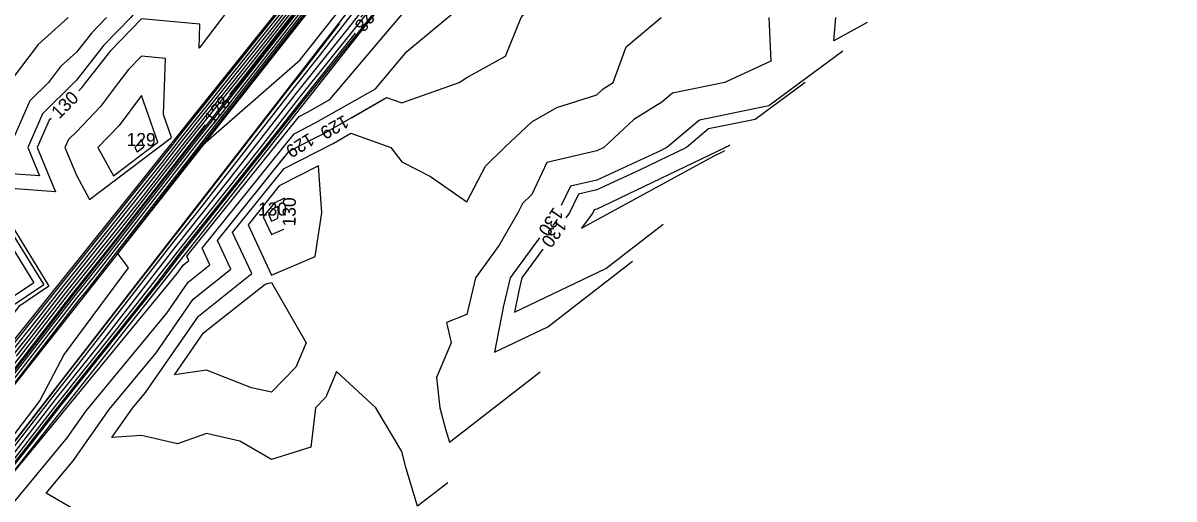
# Model space of a CAD drawing. Extents: x 2354170 to 2357230, y 866100 to 868290.
# Drawn here: x 2355531.8 to 2355708.7, y 866386 to 866459.2 of the extents above; entities that cross this region are included whole.
import ezdxf

# ---------------------------------------------------------------- set-up
doc = ezdxf.new("R2010")
doc.units = 0
for name, color, linetype in [('Default', 7, 'Continuous'), ('DTM Contours Major', 7, 'Continuous'), ('DTM Contours Major Text', 7, 'Continuous'), ('DTM Contours Minor', 7, 'Continuous'), ('DTM Contours Minor Text', 7, 'Continuous'), ('Exist DTM Breakline', 7, 'Continuous'), ('Exist DTM QL2 LIDAR Elevation Point', 7, 'Continuous'), ('Exist DTM Ridgeline', 7, 'Continuous')]:
    doc.layers.add(name, color=color, linetype=linetype)

msp = doc.modelspace()

# ---------------------------------------------------------------- linework, layer by layer
at = {"layer": 'Default'}
for points in [[(2355701.43, 866592.84), (2355679.88, 866572.94), (2355679.47, 866572.56), (2355659.43, 866554.05), (2355657.64, 866552.34), (2355657.56, 866552.26), (2355657.27, 866551.95), (2355657.06, 866551.82), (2355638.45, 866532.36), (2355637.31, 866531.16), (2355619.24, 866512.25), (2355616.59, 866509.44), (2355599.7, 866491.77), (2355595.88, 866487.71), (2355595.79, 866487.6), (2355595.68, 866487.46), (2355580.02, 866467.37), (2355577.21, 866463.86), (2355560.76, 866442.71), (2355558.78, 866440.23), (2355541.46, 866417.95), (2355540.37, 866416.59), (2355522.11, 866393.07)], [(2355700.7, 866592.69), (2355682.21, 866575.62), (2355678.79, 866572.44), (2355659.55, 866554.67), (2355656.86, 866552.17), (2355639.98, 866534.52), (2355637.02, 866531.39), (2355621.04, 866514.67), (2355616.31, 866509.66), (2355601.42, 866494.07), (2355595.61, 866487.92), (2355595.54, 866487.82), (2355595.37, 866487.61), (2355581.6, 866469.94), (2355576.87, 866464.03), (2355562.38, 866445.41), (2355558.4, 866440.43), (2355543.13, 866420.78), (2355539.95, 866416.81), (2355523.83, 866396.04)], [(2355696.16, 866591.67), (2355674.72, 866571.7), (2355672.15, 866569.33), (2355653.06, 866551.56), (2355649.16, 866547.49), (2355635.26, 866532.77), (2355631.82, 866529.17), (2355614.64, 866510.98), (2355611.71, 866507.9), (2355594.03, 866489.17), (2355594.01, 866489.15), (2355593.51, 866488.52), (2355591.06, 866485.38), (2355574.82, 866465.07), (2355572.12, 866461.59), (2355556.14, 866441.61), (2355553.15, 866437.76), (2355537.48, 866418.14), (2355534.18, 866413.89), (2355518.82, 866394.66)], [(2355691.51, 866586.32), (2355676.08, 866571.95), (2355667.95, 866564.45), (2355654.32, 866551.76), (2355646.1, 866543.17), (2355635.85, 866532.31), (2355628.22, 866524.33), (2355615.2, 866510.54), (2355608.28, 866503.29), (2355594.56, 866488.75), (2355594.52, 866488.71), (2355594.13, 866488.22), (2355587.91, 866480.24), (2355575.51, 866464.72), (2355568.87, 866456.2), (2355556.9, 866441.22), (2355549.81, 866432.1), (2355538.3, 866417.7), (2355530.73, 866407.94)], [(2355689.18, 866583.64), (2355676.75, 866572.07), (2355665.85, 866562), (2355654.96, 866551.86), (2355644.57, 866541.01), (2355636.14, 866532.08), (2355626.43, 866521.92), (2355615.48, 866510.32), (2355606.56, 866500.99), (2355594.82, 866488.55), (2355594.77, 866488.49), (2355594.44, 866488.07), (2355586.33, 866477.66), (2355575.85, 866464.55), (2355567.25, 866453.5), (2355557.27, 866441.02), (2355548.14, 866429.27), (2355538.71, 866417.48), (2355529.01, 866404.97)], [(2355521.08, 866382.07), (2355536.55, 866401.97), (2355539.81, 866406.05), (2355555, 866425.6), (2355558.57, 866430.06), (2355573.46, 866449.21), (2355577.37, 866454.09), (2355591.92, 866472.81), (2355594.43, 866475.94), (2355602.07, 866485.76), (2355617.88, 866502.5), (2355622.57, 866507.66), (2355638.82, 866524.87), (2355643.08, 866529.54), (2355659.69, 866547.13), (2355663.6, 866551.41), (2355668.54, 866556.64), (2355669.81, 866558.03), (2355688.42, 866574.61), (2355692.14, 866578)], [(2355525.32, 866386.53), (2355536.79, 866401.29), (2355544.29, 866410.68), (2355555.3, 866424.85), (2355563.32, 866434.88), (2355573.82, 866448.39), (2355582.41, 866459.13), (2355592.35, 866471.9), (2355597.75, 866478.64), (2355602.85, 866485.2), (2355613.41, 866496.37), (2355623.22, 866507.19), (2355634.85, 866519.5), (2355643.64, 866529.15), (2355656.11, 866542.36), (2355664.08, 866551.08), (2355667.93, 866555.15), (2355670.49, 866557.96), (2355685.15, 866571.01), (2355692.76, 866577.95)], [(2355684.53, 866578.29), (2355678.11, 866572.31), (2355661.65, 866557.12), (2355656.22, 866552.07), (2355641.51, 866536.68), (2355636.73, 866531.62), (2355622.83, 866517.08), (2355616.03, 866509.88), (2355603.13, 866496.38), (2355595.35, 866488.13), (2355595.28, 866488.04), (2355595.06, 866487.77), (2355583.17, 866472.51), (2355576.53, 866464.2), (2355564, 866448.11), (2355558.02, 866440.63), (2355544.8, 866423.61), (2355539.54, 866417.03), (2355525.56, 866399.02)], [(2355529.56, 866390.99), (2355537.04, 866400.61), (2355548.77, 866415.32), (2355555.6, 866424.1), (2355568.06, 866439.7), (2355574.18, 866447.56), (2355587.46, 866464.16), (2355592.78, 866471), (2355601.07, 866481.34), (2355603.63, 866484.64), (2355608.94, 866490.25), (2355623.88, 866506.72), (2355630.88, 866514.14), (2355644.19, 866528.76), (2355652.53, 866537.59), (2355664.56, 866550.75), (2355667.32, 866553.66), (2355671.18, 866557.89), (2355681.88, 866567.42), (2355693.39, 866577.91)], [(2355628.77, 866523.83), (2355624.63, 866519.5), (2355615.75, 866510.1), (2355604.85, 866498.68), (2355595.08, 866488.34), (2355595.03, 866488.26), (2355594.75, 866487.92), (2355584.75, 866475.09), (2355576.19, 866464.38), (2355565.63, 866450.8), (2355563.53, 866448.19)], [(2355582.25, 866444.6), (2355587.66, 866447.69), (2355589.98, 866446.86), (2355598.83, 866450), (2355599.98, 866450.77), (2355605.94, 866454.04), (2355608.36, 866460), (2355609.98, 866461.91), (2355615.17, 866464.81), (2355617, 866470), (2355618.06, 866471.92), (2355616.06, 866480), (2355618.55, 866488.57), (2355619.17, 866489.7), (2355620.28, 866490.99), (2355628.74, 866501.46), (2355633.84, 866508.38), (2355639.64, 866515.07)], [(2355582.44, 866469.92), (2355578.44, 866464.79), (2355577.56, 866463.68), (2355559.48, 866440.46), (2355574.36, 866453.51), (2355588.48, 866471.38), (2355592.13, 866475.27), (2355600.83, 866486.36), (2355600.84, 866486.38)], [(2355583.18, 866478.19), (2355575.65, 866468.7), (2355573.88, 866473.9), (2355572.93, 866480), (2355569.98, 866485.25), (2355567.44, 866482.55), (2355565.49, 866480), (2355564.44, 866475.55), (2355559.98, 866474.65), (2355557.47, 866472.52), (2355555.67, 866470), (2355559.98, 866461.72), (2355561.24, 866461.27), (2355563.36, 866461.25), (2355558.83, 866455.27), (2355558.97, 866458.99), (2355549.98, 866459.79), (2355545.16, 866454.82), (2355541.39, 866450), (2355540.79, 866449.19), (2355540.34, 866448.72)], [(2355580.98, 866472.17), (2355575.16, 866464.9), (2355570.49, 866458.89), (2355556.52, 866441.41), (2355551.48, 866434.93), (2355537.89, 866417.92), (2355532.45, 866410.92), (2355519.27, 866394.41), (2355518.83, 866393.84)], [(2355528.11, 866388.31), (2355533.8, 866395.45), (2355537.28, 866399.93), (2355553.25, 866419.95), (2355555.89, 866423.35), (2355572.81, 866444.52), (2355574.54, 866446.74), (2355590.39, 866466.55)], [(2355573.74, 866464.29), (2355555.77, 866441.8), (2355554.83, 866440.59), (2355537.06, 866418.36), (2355535.9, 866416.87), (2355518.36, 866394.91)], [(2355527.44, 866386.62), (2355537.61, 866398.88), (2355537.95, 866399.36), (2355555.48, 866420.63), (2355556.37, 866421.92), (2355557.27, 866422.63), (2355556.95, 866423.32), (2355574.21, 866444.8), (2355575.48, 866445.44), (2355578.93, 866447.41), (2355592.12, 866462.99)], [(2355526.64, 866381.02), (2355538.54, 866395.37), (2355541.49, 866399.55), (2355553.86, 866414.55), (2355557.16, 866419.32), (2355560.5, 866421.96), (2355559.3, 866424.53), (2355573.45, 866442.13), (2355576.8, 866443.84), (2355585.93, 866449.06), (2355590.76, 866454.76), (2355598.94, 866461.54)], [(2355544.61, 866460), (2355542.33, 866457.66), (2355539.98, 866454.65), (2355537.53, 866452.45), (2355535.67, 866450), (2355532.81, 866447.18), (2355529.98, 866440.66)], [(2355538.74, 866460), (2355534.12, 866455.86), (2355529.98, 866450.39)], [(2355597.06, 866388.5), (2355592.43, 866384.9), (2355590.68, 866390.7), (2355589.98, 866393.29), (2355586.01, 866400), (2355579.98, 866405.58), (2355578.33, 866401.65), (2355576.71, 866400), (2355576.02, 866393.97), (2355569.98, 866392.06), (2355565.12, 866394.86), (2355559.98, 866396.08), (2355555.51, 866394.47), (2355549.98, 866395.74), (2355545.43, 866395.46), (2355548.59, 866399.93), (2355550.61, 866402.38), (2355558.73, 866414.12), (2355566.95, 866420.63), (2355564, 866426.94), (2355571.92, 866436.79), (2355579.45, 866440.64), (2355582.17, 866442.2), (2355588.3, 866440), (2355589.98, 866437.8), (2355594.42, 866435.57), (2355599.98, 866431.68), (2355602.84, 866437.15), (2355605.78, 866440), (2355609.98, 866443.97), (2355613.81, 866446.18), (2355619.98, 866448.13), (2355620.94, 866449.04), (2355622.5, 866450), (2355624.47, 866455.51), (2355629.85, 866460)], [(2355646.4, 866460), (2355646.71, 866453.28), (2355639.98, 866450.15), (2355639.85, 866450.13), (2355639.67, 866450), (2355631.6, 866448.38), (2355629.98, 866447.01), (2355625.66, 866444.33), (2355621.07, 866440), (2355619.98, 866439.5), (2355612.29, 866437.69), (2355609.98, 866432.81), (2355608.55, 866431.43), (2355607.81, 866430), (2355604.98, 866425), (2355601.31, 866420), (2355599.98, 866414.35), (2355596.86, 866413.12), (2355597.6, 866410), (2355595.31, 866404.67), (2355595.85, 866400), (2355596.73, 866396.75), (2355597.34, 866394.72), (2355611.25, 866405.53)], [(2355661.53, 866459.25), (2355656.4, 866456.42), (2355656.7, 866460)], [(2355657.76, 866454.82), (2355646.41, 866446.43), (2355639.98, 866445.1), (2355635.74, 866444.24), (2355630.72, 866440), (2355629.29, 866439.32), (2355619.98, 866435.02), (2355615.92, 866434.06), (2355614.51, 866431.09)], [(2355554.62, 866441.57), (2355553.37, 866445.11), (2355553.68, 866453.71), (2355549.98, 866454.04), (2355547.99, 866451.99), (2355546.44, 866450), (2355543.67, 866446.31), (2355539.98, 866442.44), (2355538.75, 866441.23), (2355538.22, 866440), (2355539.98, 866435.75), (2355542.01, 866432.03), (2355554.62, 866441.57)], [(2355549.98, 866447.99), (2355546.56, 866443.42), (2355543.3, 866440), (2355545.66, 866435.68), (2355552.49, 866440.85), (2355549.98, 866447.99)], [(2355536.08, 866444.5), (2355535.78, 866444.2), (2355533.96, 866440), (2355536.75, 866433.23), (2355529.98, 866433.74), (2355527.98, 866432.01), (2355526.96, 866430), (2355529.98, 866428.17), (2355535.77, 866418.72), (2355531.11, 866415.6), (2355518.64, 866399.5), (2355513.82, 866403.84), (2355512.41, 866410), (2355509.98, 866411.79), (2355509.3, 866410.68), (2355508.87, 866410), (2355508.04, 866401.94), (2355504.92, 866400), (2355500.28, 866396.74)], [(2355559.79, 866443.5), (2355557.65, 866440.82), (2355546.47, 866426.44), (2355539.13, 866417.25), (2355527.28, 866401.99), (2355520.63, 866393.67), (2355508.06, 866377.44), (2355502.17, 866370.06), (2355498.55, 866364.48)], [(2355557.29, 866372.74), (2355552.79, 866380), (2355549.98, 866382.28), (2355547.89, 866382.09), (2355539.98, 866384.18), (2355535.35, 866386.88), (2355539.48, 866391.87), (2355545.04, 866399.74), (2355552.24, 866408.46), (2355557.94, 866416.72), (2355563.73, 866421.3), (2355561.65, 866425.73), (2355572.68, 866439.46), (2355577.01, 866441.67)], [(2355549.98, 866441.24), (2355549.45, 866440.54), (2355548.94, 866440), (2355549.31, 866439.33), (2355550.37, 866440.14), (2355549.98, 866441.24)], [(2355640.41, 866440.36), (2355640.13, 866440.16), (2355639.98, 866440.13), (2355639.88, 866440.11), (2355639.76, 866440), (2355620.96, 866430.99), (2355619.98, 866430.53), (2355619.55, 866430.43), (2355619.35, 866430), (2355617.6, 866427.63), (2355638.13, 866438.77), (2355639.31, 866439.34), (2355639.63, 866439.58)], [(2355571.16, 866434.12), (2355566.36, 866428.15), (2355569.98, 866420.4), (2355576.69, 866423.29), (2355577.72, 866430), (2355577.17, 866437.2), (2355571.16, 866434.12)], [(2355571.97, 866432.25), (2355570.39, 866431.45)], [(2355570.39, 866431.45), (2355568.71, 866429.35), (2355569.98, 866426.63), (2355571.89, 866427.46)], [(2355529.98, 866424.89), (2355533.44, 866419.23), (2355520.66, 866410.69)], [(2355611.16, 866426.14), (2355609.98, 866424.53), (2355606.66, 866420), (2355605.63, 866415.66), (2355604.24, 866408.54), (2355612.42, 866412.44), (2355625.44, 866422.55)], [(2355559.52, 866411.53), (2355569, 866419.03), (2355569.98, 866419.28), (2355575.3, 866410), (2355573.73, 866406.26), (2355569.98, 866402.42), (2355566.91, 866403.08), (2355559.98, 866405.77), (2355555.08, 866405.1), (2355559.52, 866411.53)]]:
    msp.add_lwpolyline(points, dxfattribs=at)
at = {"layer": 'DTM Contours Major'}
for points in [[(2355558.51, 866461.39), (2355549.98, 866462.5), (2355549.08, 866460.9), (2355548.33, 866460), (2355544.21, 866455.77), (2355539.98, 866450.35), (2355539.8, 866450.18), (2355539.66, 866450), (2355534.79, 866445.19), (2355532.53, 866440), (2355534.33, 866435.65), (2355529.98, 866435.98), (2355526.78, 866433.2), (2355525.16, 866430), (2355529.98, 866427.08), (2355535, 866418.89), (2355526.94, 866413.51), (2355519.14, 866403.43), (2355516.12, 866406.15), (2355515.25, 866410), (2355515.21, 866410.03)], [(2355651.98, 866450), (2355644.32, 866444.34), (2355639.98, 866443.44), (2355637.12, 866442.87), (2355633.73, 866440), (2355626.51, 866436.54), (2355619.98, 866433.52), (2355617.13, 866432.85), (2355615.78, 866430), (2355615.2, 866429.21)], [(2355570.14, 866430.56), (2355569.49, 866429.75), (2355569.98, 866428.71), (2355570.88, 866429.1), (2355571.02, 866430), (2355570.95, 866430.97), (2355570.14, 866430.56)], [(2355611.65, 866424.38), (2355609.98, 866422.1), (2355608.44, 866420), (2355607.96, 866417.99), (2355607.32, 866414.69), (2355621.38, 866421.41), (2355630.17, 866428.23)]]:
    msp.add_lwpolyline(points, dxfattribs=at)
at = {"layer": 'DTM Contours Minor'}
for points in [[(2355652.23, 866548.26), (2355642.53, 866538.13), (2355636.53, 866531.77), (2355624.03, 866518.69), (2355615.85, 866510.03), (2355604.28, 866497.91), (2355595.17, 866488.27), (2355595.11, 866488.19), (2355594.85, 866487.87), (2355584.23, 866474.23), (2355576.3, 866464.32), (2355565.08, 866449.91), (2355557.77, 866440.76), (2355545.91, 866425.5), (2355539.27, 866417.18), (2355526.71, 866401), (2355522.78, 866396.09)], [(2355632.12, 866525.36), (2355618.04, 866510.64), (2355616.77, 866509.3), (2355598.56, 866490.23), (2355596.05, 866487.57), (2355595.96, 866487.45), (2355595.89, 866487.36), (2355578.97, 866465.65), (2355577.44, 866463.74), (2355559.68, 866440.92), (2355559.03, 866440.1), (2355546.3, 866423.73), (2355547.93, 866421.51), (2355538.1, 866408.23), (2355534.35, 866401.15), (2355518.37, 866380.18), (2355517.13, 866378.25), (2355513.56, 866372.86), (2355512.56, 866371.68), (2355510.97, 866369.31)], [(2355608.41, 866503.92), (2355594.29, 866488.96), (2355594.27, 866488.93), (2355593.82, 866488.37), (2355589.49, 866482.81), (2355575.16, 866464.9), (2355570.49, 866458.89), (2355556.52, 866441.41), (2355551.48, 866434.93), (2355537.89, 866417.92), (2355532.45, 866410.92), (2355519.27, 866394.41), (2355513.4, 866386.84), (2355500.67, 866370.9), (2355498.66, 866367.8), (2355494.34, 866360.72), (2355489.81, 866353.71), (2355485.43, 866346.53)], [(2355577.01, 866441.67), (2355578.13, 866442.24), (2355587.66, 866447.69), (2355589.98, 866446.86), (2355598.83, 866450), (2355599.98, 866450.77), (2355605.94, 866454.04), (2355608.36, 866460)], [(2355465.64, 866295.65), (2355466.44, 866296.93), (2355467.87, 866299.21), (2355482.44, 866322.33), (2355483.46, 866323.96), (2355498.44, 866347.73), (2355499.08, 866348.75), (2355514.44, 866373.12), (2355514.49, 866373.2), (2355517.99, 866378.75), (2355518.26, 866379.09), (2355536.39, 866402.43), (2355536.82, 866402.96), (2355554.8, 866426.09), (2355555.4, 866426.84), (2355573.22, 866449.76), (2355574, 866450.74), (2355580.49, 866459.09)], [(2355467.19, 866294.81), (2355467.69, 866295.6), (2355480.66, 866316.28), (2355483.66, 866321.04), (2355495.84, 866340.45), (2355499.63, 866346.47), (2355511.07, 866364.7), (2355515.61, 866371.9), (2355517.56, 866375.01), (2355518.62, 866376.69), (2355532.38, 866393.96), (2355537.2, 866400.16), (2355551.76, 866418.4), (2355555.79, 866423.6), (2355571.23, 866442.92), (2355574.42, 866447.01), (2355582.87, 866457.58)], [(2355549.98, 866441.24), (2355549.45, 866440.54), (2355548.94, 866440), (2355549.31, 866439.33), (2355550.37, 866440.14), (2355549.98, 866441.24)], [(2355539.98, 866384.18), (2355535.35, 866386.88), (2355539.48, 866391.87), (2355545.04, 866399.74), (2355552.24, 866408.46), (2355557.94, 866416.72), (2355563.73, 866421.3), (2355561.65, 866425.73), (2355571.97, 866438.57)]]:
    msp.add_lwpolyline(points, dxfattribs=at)
at = {"layer": 'Exist DTM Breakline'}
for points in [[(2355361.74, 866117.94), (2355394.04, 866183.66), (2355433.6, 866257.62), (2355503.45, 866369.34), (2355596.39, 866487.31), (2355657.48, 866552.26), (2355736.19, 866624.67), (2355827.16, 866697.76), (2355869.57, 866728.83), (2355917.57, 866765.21), (2355965.06, 866802.76)], [(2355368.43, 866114.28), (2355394.89, 866169.22), (2355434.21, 866246.39), (2355517.97, 866378.8), (2355601.38, 866486.27), (2355669.14, 866558.09), (2355738.69, 866620.01), (2355814.81, 866681.57), (2355823.8, 866686.8), (2355859.09, 866669.85), (2355910.74, 866643.97)]]:
    msp.add_lwpolyline(points, dxfattribs=at)
at = {"layer": 'Exist DTM QL2 LIDAR Elevation Point'}
for p, q in [((2355539.98, 866450), (2355539.98, 866450)), ((2355549.98, 866450), (2355549.98, 866450)), ((2355589.98, 866450), (2355589.98, 866450)), ((2355599.98, 866450), (2355599.98, 866450)), ((2355609.98, 866450), (2355609.98, 866450)), ((2355619.98, 866450), (2355619.98, 866450)), ((2355629.98, 866450), (2355629.98, 866450)), ((2355639.98, 866450), (2355639.98, 866450)), ((2355649.98, 866450), (2355649.98, 866450)), ((2355539.98, 866440), (2355539.98, 866440)), ((2355549.98, 866440), (2355549.98, 866440)), ((2355579.98, 866440), (2355579.98, 866440)), ((2355589.98, 866440), (2355589.98, 866440)), ((2355599.98, 866440), (2355599.98, 866440)), ((2355609.98, 866440), (2355609.98, 866440)), ((2355619.98, 866440), (2355619.98, 866440)), ((2355629.98, 866440), (2355629.98, 866440)), ((2355639.98, 866440), (2355639.98, 866440)), ((2355539.98, 866430), (2355539.98, 866430)), ((2355569.98, 866430), (2355569.98, 866430)), ((2355579.98, 866430), (2355579.98, 866430)), ((2355589.98, 866430), (2355589.98, 866430)), ((2355599.98, 866430), (2355599.98, 866430)), ((2355609.98, 866430), (2355609.98, 866430)), ((2355619.98, 866430), (2355619.98, 866430)), ((2355569.98, 866420), (2355569.98, 866420)), ((2355579.98, 866420), (2355579.98, 866420)), ((2355589.98, 866420), (2355589.98, 866420)), ((2355599.98, 866420), (2355599.98, 866420)), ((2355609.98, 866420), (2355609.98, 866420)), ((2355559.98, 866410), (2355559.98, 866410)), ((2355569.98, 866410), (2355569.98, 866410)), ((2355579.98, 866410), (2355579.98, 866410)), ((2355589.98, 866410), (2355589.98, 866410)), ((2355599.98, 866410), (2355599.98, 866410)), ((2355549.98, 866400), (2355549.98, 866400)), ((2355559.98, 866400), (2355559.98, 866400)), ((2355569.98, 866400), (2355569.98, 866400)), ((2355579.98, 866400), (2355579.98, 866400)), ((2355589.98, 866400), (2355589.98, 866400)), ((2355599.98, 866400), (2355599.98, 866400)), ((2355539.98, 866390), (2355539.98, 866390)), ((2355549.98, 866390), (2355549.98, 866390)), ((2355559.98, 866390), (2355559.98, 866390)), ((2355569.98, 866390), (2355569.98, 866390)), ((2355579.98, 866390), (2355579.98, 866390)), ((2355589.98, 866390), (2355589.98, 866390))]:
    msp.add_line(p, q, dxfattribs=at)
at = {"layer": 'Exist DTM Ridgeline'}
for points in [[(2355359.21, 866119.33), (2355391.05, 866186.52), (2355431.02, 866258.6), (2355499.33, 866371.65), (2355593.69, 866489.44), (2355651.92, 866551.38), (2355734.91, 866627), (2355826.44, 866700.14), (2355852.87, 866722.79), (2355915.41, 866769.54), (2355965.69, 866805.26), (2355970.96, 866806.36)], [(2355370.78, 866112.99), (2355397.74, 866167.09), (2355435.8, 866244.69), (2355518.89, 866375.79), (2355604.42, 866484.07), (2355673.04, 866557.71), (2355740.7, 866618.52), (2355815.66, 866679.47), (2355822.99, 866684.57), (2355856.95, 866667.18), (2355908.26, 866642.02)]]:
    msp.add_lwpolyline(points, dxfattribs=at)

# ---------------------------------------------------------------- texts
at = {"layer": 'Default'}
for s, rotation, p in [('130', 44.7729, (2355537.32, 866444.31)), ('128', 51.3666, (2355561.02, 866443.44)), ('129', 209.1818, (2355581.14, 866445.09)), ('130', 89.0706, (2355573.65, 866427.88)), ('130', 235.8936, (2355613.37, 866430.98))]:
    msp.add_text(s, height=2, rotation=rotation, dxfattribs=at).set_placement(p)
msp.add_text('129', height=2, dxfattribs=at).set_placement((2355547.7, 866440.24))
at = {"layer": 'DTM Contours Major Text'}
msp.add_text('130', height=2, dxfattribs=at).set_placement((2355567.89, 866429.56))
msp.add_text('130', height=2, rotation=233.7068, dxfattribs=at).set_placement((2355613.95, 866429.2))
at = {"layer": 'DTM Contours Minor Text'}
for s, rotation, p in [('128', 231.3308, (2355585.39, 866462.33)), ('129', 211.6172, (2355575.76, 866442.35))]:
    msp.add_text(s, height=2, rotation=rotation, dxfattribs=at).set_placement(p)
msp.add_text('129', height=2, dxfattribs=at).set_placement((2355547.7, 866440.24))

doc.saveas('drawing.dxf')
